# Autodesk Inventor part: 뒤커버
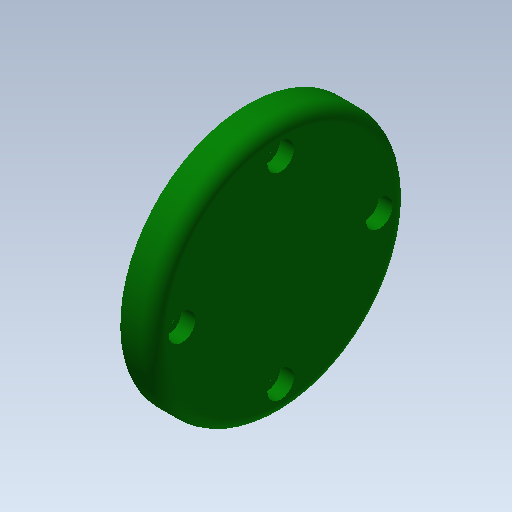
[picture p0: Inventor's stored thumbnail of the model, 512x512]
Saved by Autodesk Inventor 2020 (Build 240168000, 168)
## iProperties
Created: 2015-09
Part Number: 뒤커버
Material: 알루미늄 6061
Document SubType Name: Modeling
Designer: mduedu
Density: 2.71 g/cm^3
Mass: 54.0417 g
Surface Area: 84.9688 cm^2
Volume: 19.9416 cm^3
Appearance: 진녹색
Author: mduedu
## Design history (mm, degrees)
sketch "스케치1"
  geometry: L1 (-15.5, 47)-(-15.5, 78); L2 (-15.5, 78)-(-23.5, 78); L3 (-23.5, 78)-(-23.5, 67); L4 (-27.5, 67)-(-27.5, 47); L5 (-79.5, 39.5)-(-79.5, 54.5) reference; L6 (48.5, 54.5)-(48.5, 39.5) reference; L7 (-79.5, 47)-(48.5, 47); L8 (-23.5, 67)-(-27.5, 67); L9 (-27.5, 47)-(-15.5, 47); 1 further point
  constraints: 14 end point, 4 midpoint, 3 parallel, 1 collinear, 1 point on line, 1 vertical
  dimensions: "d6" = 62 diameter of L2 L7; "d7" = 8 distance of L1.end L2.end; "d8" = 40 diameter of L3.end L7; "d32" = 12 distance between parallel lines of L1 L4
revolve "회전1" sketch "스케치1" stored, may be unused: angle "d4" = 90 deg
sketch "스케치4"
  geometry: C1 r 31 at (0, 0) reference; 2 further points
  constraints: 1 coincident
hole "구멍3" sketch "스케치4" at (0, 0) diameter "d33" = 33; stored, may be unused: countersink angle "d37" = 90 deg, drill point angle "d39" = 0 deg; dims "d34" = 6, "d35" = 4, "d36" = 2, "d38" = 5
fillet "모깎기4" dims "d56" = 3
chamfer "모따기2" distance "d41" = 1; stored, may be unused: second distance "d42" = 2, angle "d43" = 45 deg
sketch "스케치5" dims "d44" = 48
  geometry: C1 r 31 at (0, 0) reference; 6 further points
  constraints: 2 vertical alignment, 1 coincident, 7 other
  dimensions: "d47" = 360 deg dimension on C1.centre point (0, -24) (derived)
sketch "스케치6"
  geometry: C1 r 28 at (0, 0) reference; A1 r 24 centre (0, 0) between (24, 0) and (0, 24); 2 further points
  constraints: 4 point on circle, 2 horizontal alignment, 2 vertical alignment, 1 centre point, 1 coincident
  dimensions: "d57" = 48 diameter of A1
hole "구멍4" sketch "스케치6" at (24, 0), (0, 24), (-24, 0), (0, -24) diameter "d49" = 3.4; stored, may be unused: countersink angle "d53" = 90 deg, drill point angle "d55" = 0 deg; dims "d50" = 6, "d51" = 6.5, "d52" = 3.4, "d54" = 8
node "솔리드1"
node "참조1"
node "참조2"
